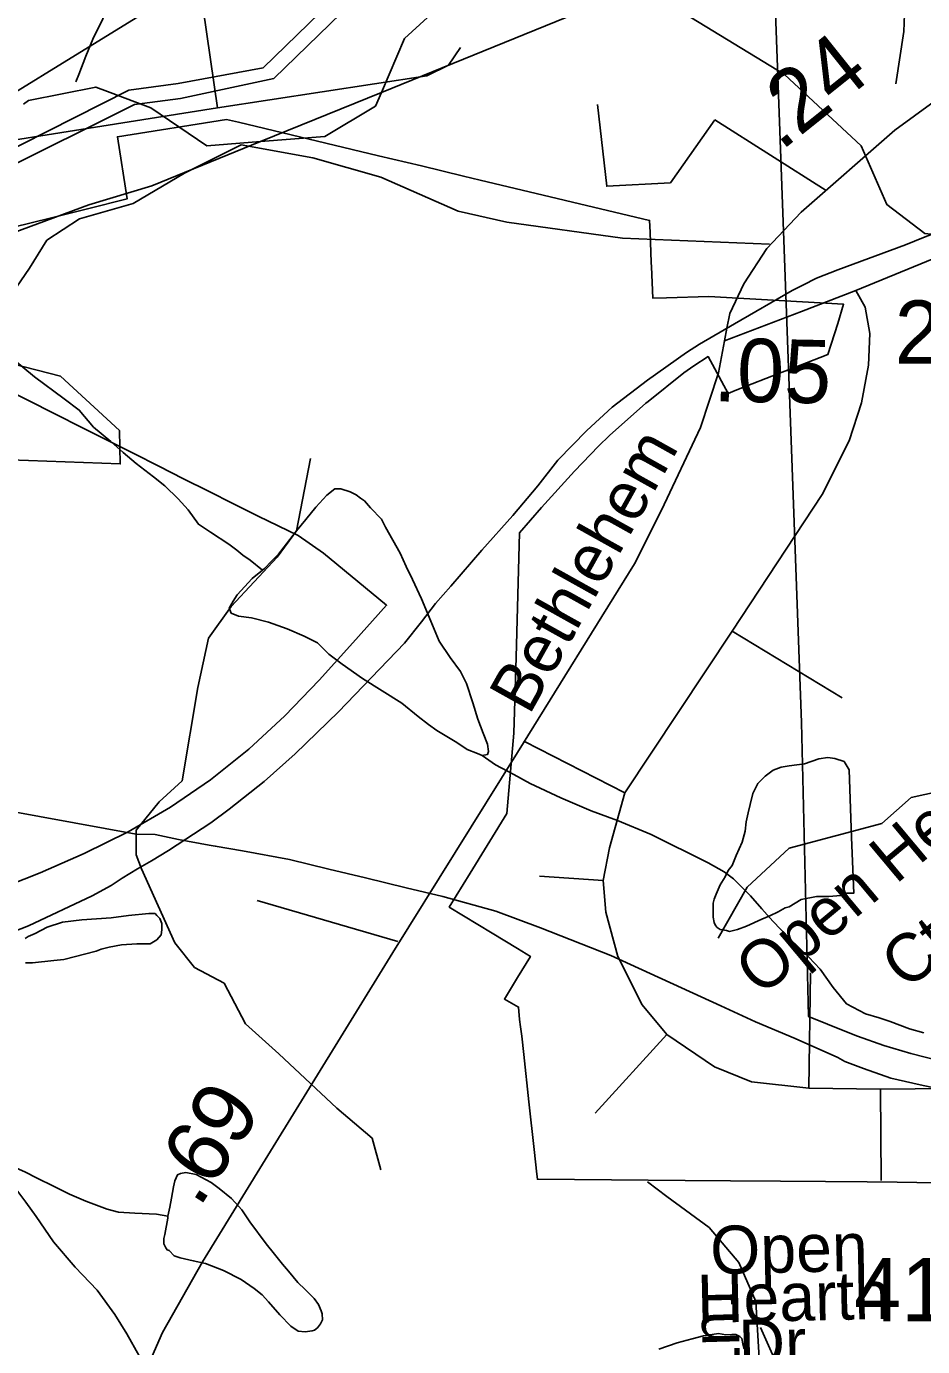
# Model space of a CAD drawing. Extents: x 2169602 to 2449496, y 721995 to 810662.
# Drawn here: x 2391367 to 2393135, y 804152 to 806757 of the extents above; entities that cross this region are included whole.
import ezdxf

# ---------------------------------------------------------------- set-up
doc = ezdxf.new("R2010")
doc.units = 0
doc.layers.add('Default', color=7, linetype='Continuous')

msp = doc.modelspace()

# ---------------------------------------------------------------- linework, layer by layer
at = {"layer": 'Default'}
for p, q in [((2392580.3, 806835.4), (2392067.6, 806626.8)), ((2391527.1, 806628.9), (2391586.4, 806606.4)), ((2392067.6, 806626.8), (2391829.1, 806529.8)), ((2391586.4, 806606.4), (2391612.6, 806596.5)), ((2392725.6, 806573.1), (2392638.2, 806448.5)), ((2392944.9, 806433.4), (2392725.6, 806573.1)), ((2392543.3, 806339.1), (2392314.9, 806370.8)), ((2393004, 806236), (2393281.6, 806350.5)), ((2392833.4, 806327.5), (2392543.3, 806339.1)), ((2392968, 806276.6), (2393101.4, 806326)), ((2392695.4, 806129.8), (2392764.1, 806170.5)), ((2392099.7, 804950.8), (2391822.3, 805031.9)), ((2391646, 804409), (2391624.1, 804412.8))]:
    msp.add_line(p, q, dxfattribs=at)
for points in [[(2391306.5, 806466.6), (2391580.7, 806603.4), (2391671.2, 806615.2), (2391855.2, 806654.1), (2392076.5, 806869.3), (2392429, 807051.7), (2392765.5, 807215.9), (2392830.2, 807238.5), (2392846, 806766.4), (2392896.5, 805383.2), (2392910.2, 804803.1), (2392985.5, 804772.6), (2393006.7, 804764.2), (2393059.2, 804746.1), (2393112.5, 804730.1), (2393166.2, 804716.1), (2393220.5, 804704.1), (2393242.7, 804699.7), (2393269.2, 804694.2), (2393329.5, 804686.7), (2393433.5, 804681.9), (2393504.7, 804684.1)], [(2391306.5, 806466.6), (2391580.7, 806603.4), (2391671.2, 806615.2), (2391855.2, 806654.1), (2392076.5, 806869.3), (2392429, 807051.7), (2392765.5, 807215.9), (2392830.2, 807238.5), (2392846, 806766.4), (2392896.5, 805383.2), (2392910.2, 804803.1), (2392985.5, 804772.6), (2393006.7, 804764.2), (2393059.2, 804746.1), (2393112.5, 804730.1), (2393166.2, 804716.1), (2393220.5, 804704.1), (2393242.7, 804699.7), (2393269.2, 804694.2), (2393329.5, 804686.7), (2393433.5, 804681.9), (2393504.7, 804684.1)], [(2391611.8, 806941.8), (2391606, 806939.8), (2391586.3, 806913.6), (2391564.2, 806874.7), (2391545.5, 806832.1), (2391530.2, 806798.3), (2391518.1, 806772.2), (2391498.4, 806732.2), (2391484.6, 806698.2), (2391470.5, 806662.1), (2391464.7, 806648)], [(2391744.2, 806596.2), (2391693.9, 806942.4)], [(2391302.5, 806496.6), (2391569.5, 806631.3), (2391666.5, 806644.7), (2391834.5, 806675.6), (2392058.7, 806893.9)], [(2391302.5, 806496.6), (2391569.5, 806631.3), (2391666.5, 806644.7), (2391834.5, 806675.6), (2392058.7, 806893.9)], [(2393093.3, 806895.8), (2393101.2, 806816.3), (2393098.6, 806747.4), (2393082.7, 806644)], [(2392067.6, 806626.8), (2392113.1, 806733.3), (2392204, 806816.8), (2392222.1, 806872.4)], [(2393763.4, 806849), (2393609.6, 806863.6), (2393538.4, 806853.2), (2393452.6, 806816.5), (2393330.7, 806734.8), (2393080.6, 806552.6), (2392895.9, 806390.3), (2392827.9, 806319.1), (2392782.9, 806249), (2392754.9, 806190.9), (2392749.4, 806161.5)], [(2393194.1, 806342.4), (2393140, 806348.2), (2393065, 806405.5), (2393014.1, 806521.4), (2392863, 806662.2), (2392580.3, 806835.4)], [(2391643.7, 806811.6), (2391144.7, 806504.4)], [(2391643.7, 806811.6), (2391144.7, 806504.4)], [(2391744.2, 806596.2), (2392157.4, 806659.8), (2392199.8, 806681), (2392223.7, 806715.5)], [(2391361.7, 806603.8), (2391371, 806610.8), (2391504.1, 806637.6), (2391527.1, 806628.9)], [(2391829.1, 806529.8), (2391956, 806539.7), (2392056.1, 806600.1), (2392067.6, 806626.8)], [(2390891.2, 806474.3), (2390925.7, 806474.3), (2391005.1, 806479.6), (2391744.2, 806596.2)], [(2391612.6, 806596.5), (2391723.1, 806521.6), (2391829.1, 806529.8)], [(2392638.2, 806448.5), (2392512.1, 806441.8), (2392494, 806603.2)], [(2391341.7, 806360.9), (2391413.7, 806378.8), (2391487.7, 806397.3), (2391565.7, 806416.6), (2391546.7, 806539.3), (2391761.7, 806573.6), (2391785.4, 806568), (2392062.2, 806501.8), (2392146.4, 806481.8), (2392229.4, 806461.9), (2392262.4, 806454), (2392596.7, 806374.2), (2392597.7, 806351.3), (2392600.2, 806291.4), (2392600.7, 806282.8), (2392603.4, 806220.7), (2392630.2, 806221.6), (2392713.9, 806224.4), (2392979.7, 806208.8), (2392967.9, 806171.1), (2392948.7, 806109.4), (2392879.7, 806083), (2392858.2, 806074.8), (2392825.9, 806062.2), (2392799.2, 806051.6), (2392788.7, 806047.6), (2392760.9, 806036.6), (2392751.7, 806033), (2392712.2, 806105.4), (2392683.9, 806087.2), (2392664.4, 806073.3), (2392593.9, 806017.1), (2392589.4, 806013.3), (2392517.4, 805949.8), (2392495.7, 805929), (2392448.4, 805879.3), (2392383.2, 805807.4), (2392339.9, 805757.9), (2392333.4, 805512.2), (2392329.2, 805362.6), (2392315.4, 805203.5), (2392242.7, 805085.7), (2392201.4, 805018.9), (2392285.9, 804967.6), (2392336.2, 804937.2), (2392361.7, 804921.7), (2392336.2, 804879.8), (2392310.4, 804837.6), (2392338.2, 804821.5), (2392340.2, 804797.3), (2392342.2, 804782.4), (2392344.4, 804764), (2392348.7, 804728.3), (2392358.7, 804634.9), (2392368.9, 804540.4), (2392374.4, 804491.8), (2392375.4, 804481.8), (2392521.4, 804480.5), (2392666.7, 804479.3), (2392756.7, 804478.6)], [(2391341.7, 806360.9), (2391413.7, 806378.8), (2391487.7, 806397.3), (2391565.7, 806416.6), (2391546.7, 806539.3), (2391761.7, 806573.6), (2391785.4, 806568), (2392062.2, 806501.8), (2392146.4, 806481.8), (2392229.4, 806461.9), (2392262.4, 806454), (2392596.7, 806374.2), (2392597.7, 806351.3), (2392600.2, 806291.4), (2392600.7, 806282.8), (2392603.4, 806220.7), (2392630.2, 806221.6), (2392713.9, 806224.4), (2392979.7, 806208.8), (2392967.9, 806171.1), (2392948.7, 806109.4), (2392879.7, 806083), (2392858.2, 806074.8), (2392825.9, 806062.2), (2392799.2, 806051.6), (2392788.7, 806047.6), (2392760.9, 806036.6), (2392751.7, 806033), (2392712.2, 806105.4), (2392683.9, 806087.2), (2392664.4, 806073.3), (2392593.9, 806017.1), (2392589.4, 806013.3), (2392517.4, 805949.8), (2392495.7, 805929), (2392448.4, 805879.3), (2392383.2, 805807.4), (2392339.9, 805757.9), (2392333.4, 805512.2), (2392329.2, 805362.6), (2392315.4, 805203.5), (2392242.7, 805085.7), (2392201.4, 805018.9), (2392285.9, 804967.6), (2392336.2, 804937.2), (2392361.7, 804921.7), (2392336.2, 804879.8), (2392310.4, 804837.6), (2392338.2, 804821.5), (2392340.2, 804797.3), (2392342.2, 804782.4), (2392344.4, 804764), (2392348.7, 804728.3), (2392358.7, 804634.9), (2392368.9, 804540.4), (2392374.4, 804491.8), (2392375.4, 804481.8), (2392521.4, 804480.5), (2392666.7, 804479.3), (2392756.7, 804478.6)], [(2391829.1, 806529.8), (2391614.3, 806442.5), (2391490.6, 806405), (2390221, 805935.1), (2390136.1, 805905.1)], [(2391251.7, 806110.4), (2391253, 806114.9), (2391311.1, 806190.5), (2391373.5, 806280.3), (2391407.2, 806335.2), (2391472, 806377.7), (2391578.1, 806407.6), (2391679.1, 806467.5), (2391790.8, 806523.2)], [(2391790.8, 806523.2), (2391932.3, 806497.8), (2392066.2, 806459.5), (2392219.3, 806392.5), (2392314.9, 806370.8)], [(2393101.4, 806326), (2393137.3, 806340.5), (2393195.1, 806363.1)], [(2392764.1, 806170.5), (2392878.3, 806235.8), (2392899.3, 806246.6), (2392926, 806260.2), (2392968, 806276.6)], [(2392744.8, 806136.7), (2392896.7, 806194.8), (2393004, 806236)], [(2393004, 806236), (2393022, 806202.9), (2393031.1, 806150.9), (2393028.8, 806088.6), (2393015.2, 806014), (2392990.4, 805939.5), (2392937.2, 805833.1), (2392759.7, 805563.8)], [(2392749.4, 806161.5), (2392744.8, 806136.7)], [(2391298.4, 804953.5), (2391371, 804982.2), (2391496.6, 805041.2), (2391534.4, 805061.7), (2391556.1, 805075.8), (2391586.1, 805094.2), (2391613.8, 805110.4), (2391647.6, 805130.7), (2391731.1, 805185.6), (2391766.9, 805212.1), (2391836.2, 805266.9), (2391897.7, 805321.4), (2391982.8, 805404.2), (2392113.4, 805539.8), (2392147, 805582.1), (2392174.6, 805618.3), (2392204.3, 805652.7), (2392265.5, 805723.2), (2392326.9, 805792), (2392376.3, 805850.5), (2392415.7, 805900.9), (2392472.7, 805959.5), (2392522.7, 806005.9), (2392592.4, 806059.1), (2392669.5, 806113.5), (2392695.4, 806129.8)], [(2392744.8, 806136.7), (2392732.9, 806073.6), (2392697.4, 805965.7), (2392620.5, 805802.4), (2392567.1, 805696.6), (2392336.4, 805323.8), (2392089.9, 804929.1), (2391833.1, 804511.3), (2391714.8, 804318.6), (2391635.8, 804179.3), (2391561.5, 804009.7), (2391540.6, 803916.5), (2391505.5, 803843.2), (2391448, 803659.9), (2391386.8, 803479.8), (2391371.1, 803380.4), (2391370, 803296.6), (2391381, 803121.7), (2391397.2, 802941.6)], [(2391299.2, 805049.1), (2391394.4, 805086.9), (2391481.2, 805124.5), (2391568.2, 805167.3), (2391651.4, 805216.1), (2391730.7, 805270.3), (2391805.7, 805330.9), (2391876.9, 805396.5), (2391944.7, 805467), (2392011.4, 805540.3), (2392077.9, 805614.6), (2392062.4, 805627.4), (2391953.2, 805717.4), (2391903.2, 805752.1), (2391824.7, 805790.3), (2391775.7, 805815), (2391726.4, 805839.8), (2391677.4, 805864.5), (2391628.2, 805889.3), (2391579.2, 805914), (2391530.2, 805938.8), (2391466.2, 805970.9), (2391434.9, 805986.7), (2391201.2, 806104.6)], [(2391299.2, 805049.1), (2391394.4, 805086.9), (2391481.2, 805124.5), (2391568.2, 805167.3), (2391651.4, 805216.1), (2391730.7, 805270.3), (2391805.7, 805330.9), (2391876.9, 805396.5), (2391944.7, 805467), (2392011.4, 805540.3), (2392077.9, 805614.6), (2392062.4, 805627.4), (2391953.2, 805717.4), (2391903.2, 805752.1), (2391824.7, 805790.3), (2391775.7, 805815), (2391726.4, 805839.8), (2391677.4, 805864.5), (2391628.2, 805889.3), (2391579.2, 805914), (2391530.2, 805938.8), (2391466.2, 805970.9), (2391434.9, 805986.7), (2391201.2, 806104.6)], [(2391251.7, 806110.4), (2391267.2, 806109.6), (2391434.3, 806066.8), (2391551.1, 805959.4), (2391552.2, 805893.8), (2391335.2, 805901.5), (2391216.4, 805988.1)], [(2391617.9, 805868.3), (2391583.9, 805894.2), (2391557.8, 805916.4), (2391533.8, 805938.2), (2391499.8, 805966.1), (2391471.5, 806000), (2391441.6, 806022), (2391383.3, 806065.6), (2391333.1, 806107.3)], [(2391583.9, 805163.1), (2391583.9, 805171), (2391629, 805226.6), (2391674.2, 805268.3), (2391705.4, 805452.5), (2391726.3, 805549.8), (2391771.4, 805612.4), (2391861.7, 805709.7), (2391899.9, 805761.8), (2391927.7, 805904.3)], [(2391832.8, 805683.7), (2391808.8, 805703.5), (2391794.5, 805713.5), (2391782.4, 805723.4), (2391766.6, 805735.1), (2391730.5, 805758.8), (2391706.5, 805774.6), (2391686, 805802.9), (2391666.3, 805824.5), (2391640.1, 805850.4), (2391617.9, 805868.3)], [(2392266.5, 805317.9), (2392276.7, 805320), (2392279, 805326.2), (2392276.7, 805340.3), (2392268.3, 805362.3), (2392258.1, 805390.1), (2392248.2, 805422.1), (2392235.7, 805460.1), (2392223.6, 805483.8), (2392203.5, 805511.6), (2392181.8, 805543.7), (2392165, 805583.6), (2392146.7, 805627.3), (2392128.9, 805665.3), (2392116.6, 805691.1), (2392104.5, 805717.3), (2392076, 805769), (2392068, 805784.8), (2392046.3, 805806.8), (2392034.2, 805820.8), (2392026.2, 805826.4), (2392017.8, 805832.5), (2392006.1, 805838.4), (2391987.8, 805844.4), (2391975.5, 805844.2), (2391959.9, 805832), (2391938, 805808.1), (2391918.3, 805783.9), (2391900.3, 805761.9), (2391880.6, 805735.7), (2391864.4, 805715.8), (2391850.6, 805701.7), (2391836.9, 805687.5), (2391832.8, 805683.7)], [(2391832.8, 805683.7), (2391812.7, 805667.3), (2391783, 805635.2), (2391775.2, 805623), (2391767.2, 805609.2), (2391771.1, 805599.3), (2391785.4, 805593.1), (2391811.1, 805589.6), (2391845.1, 805581.6), (2391881.6, 805568), (2391915.2, 805554), (2391941.5, 805540.3), (2391963.8, 805518.3), (2391989.9, 805498.5), (2392030.1, 805470.5), (2392108.2, 805421.4), (2392140, 805395.4), (2392160.3, 805379.4), (2392176.7, 805367.6), (2392196.8, 805355.6), (2392216.5, 805343.8), (2392236.8, 805330.1), (2392257.1, 805322.2), (2392266.5, 805317.9)], [(2392759.7, 805563.8), (2392548, 805244.2)], [(2392759.7, 805563.8), (2392976.8, 805432)], [(2390262.1, 805404.2), (2391583.9, 805163.1), (2391621, 805162), (2391667.5, 805152.7), (2391727.6, 805141.3), (2391739.6, 805139.4), (2391793.8, 805129.9), (2391886, 805112.8), (2391964.2, 805093.8), (2392036.4, 805076.5), (2392116.6, 805057.3), (2392188.9, 805040), (2392293.1, 805011.1), (2392381.6, 804978.1), (2392520, 804923.4), (2392737.2, 804823.8), (2392805.5, 804792.6), (2392883.8, 804759.4), (2392968.2, 804722.3), (2392982.3, 804714.4), (2393018.6, 804700.7), (2393072.8, 804681.3), (2393130.9, 804668), (2393205, 804652.6)], [(2392548, 805244.2), (2392350, 805345.9)], [(2393137.8, 804771.1), (2393109.7, 804779), (2393071.5, 804792.9), (2393049.6, 804800.7), (2393023.1, 804808.4), (2392985.2, 804828.3), (2392959.2, 804860.2), (2392933.3, 804896.2), (2392910.8, 804919.9), (2392872.4, 804957.7), (2392840.2, 804991.4), (2392818.3, 805015.4), (2392795.9, 805041.1), (2392782, 805054.9), (2392762.1, 805075), (2392743.9, 805088.7), (2392712.1, 805106.5), (2392599.7, 805162), (2392533.3, 805189.6), (2392481.4, 805209.1), (2392421.5, 805234.9), (2392361, 805262.7), (2392329.2, 805280.4), (2392292.9, 805300.1), (2392266.5, 805317.9)], [(2392995.5, 805156.4), (2392990.6, 805290.2), (2392980.6, 805306.3), (2392962.3, 805312.3), (2392948.2, 805314), (2392930.5, 805311.8), (2392902.4, 805301.9), (2392872.3, 805297.5), (2392856.7, 805295.4), (2392840.9, 805289.3), (2392824.7, 805277.1), (2392810.6, 805263), (2392800.7, 805243), (2392795, 805221.2), (2392791.1, 805205.1), (2392787.2, 805187), (2392785.6, 805169), (2392779.2, 805146.9), (2392767.7, 805121), (2392759.7, 805101.2), (2392751.7, 805091), (2392746, 805078.9), (2392735.9, 805063), (2392727.9, 805044.7), (2392724, 805034.7), (2392722.4, 805026.9), (2392722.4, 805016.7), (2392722, 805004.6), (2392722.4, 804998.9), (2392724.5, 804988.9), (2392726.5, 804982.9), (2392730.4, 804978.6), (2392736.1, 804974.9), (2392748.7, 804973), (2392754.2, 804971), (2392762.2, 804973), (2392770.2, 804975), (2392788.2, 804981.2), (2392818.2, 804995.4), (2392834.2, 805001.5), (2392850.4, 805009.6), (2392864.1, 805017.7), (2392872.1, 805019.7), (2392896.1, 805033.9), (2392926, 805039.9), (2392950.2, 805039.9), (2392974, 805042), (2392986.1, 805046.2), (2392999.6, 805046.2), (2392995.5, 805156.4)], [(2393325.8, 805202), (2393263.1, 805268.2), (2393113.2, 805235.2), (2393055.2, 805183.9), (2392872.1, 805135.3), (2392789.3, 805058.2), (2392732.2, 804957.7)], [(2392548, 805244.2), (2392517.5, 805135.8), (2392505, 805071.3)], [(2391865.2, 804729.6), (2391799.2, 804788.7), (2391757.5, 804868.6), (2391698.5, 804899.9), (2391660.3, 804948.6), (2391594.3, 805094.5), (2391583.9, 805122.3), (2391583.9, 805163.1)], [(2392505, 805071.3), (2392379.5, 805080.3)], [(2392505, 805071.3), (2392510.7, 805009), (2392534.4, 804921.3), (2392581.9, 804826.3), (2392630.6, 804767.5)], [(2391364.8, 804957.2), (2391370.9, 804961.1), (2391384.6, 804967.2), (2391408.4, 804979.4), (2391438.6, 804989.5), (2391476.7, 804993.8), (2391534.7, 804998), (2391568.6, 805002.2), (2391608.8, 805006.3), (2391620.9, 805006.5), (2391624.8, 805002.6), (2391630.5, 804996.5), (2391634.4, 804986.6), (2391634.6, 804974.4), (2391633, 804964.5), (2391624.8, 804954.4), (2391611.2, 804946.3), (2391584.8, 804946.3), (2391554.8, 804944.3), (2391530.6, 804939.8), (2391514.6, 804936.2), (2391505, 804932)], [(2391505, 804932), (2391441.2, 804915.7), (2391421.3, 804913.4), (2391378.9, 804909.2), (2391371.3, 804909.2), (2391365.4, 804909.2)], [(2392911.2, 804661.8), (2392914.6, 804889.2)], [(2392630.6, 804767.5), (2392489.2, 804612.4)], [(2392630.6, 804767.5), (2392724.6, 804703.6), (2392798.1, 804674.2), (2392911.2, 804661.8)], [(2391865.2, 804729.6), (2391979.8, 804621.9), (2392049.2, 804562.8), (2392066.6, 804500.2)], [(2392911.2, 804661.8), (2393052.6, 804659.5)], [(2393052.6, 804659.5), (2393258.4, 804661.8)], [(2393052.6, 804659.5), (2393053.7, 804479.6)], [(2391624.1, 804412.8), (2391580.8, 804415.2), (2391548.6, 804416.9), (2391526.3, 804423.1), (2391484.4, 804438.8), (2391452.2, 804452.5), (2391420.4, 804468.3), (2391388.3, 804484.1), (2391363.9, 804496.3), (2391314, 804518.1)], [(2391625.9, 804084.7), (2391616.1, 804094.7), (2391589.8, 804133.2), (2391565.6, 804177), (2391541.4, 804215.1), (2391507, 804262.9), (2391463.1, 804308.5), (2391420.9, 804358.3), (2391386.6, 804408.1), (2391366.3, 804436.3), (2391342.1, 804468), (2391314, 804518.1)], [(2391646, 804409), (2391650.1, 804426.7), (2391653.6, 804444.8), (2391657.7, 804466.9), (2391659.7, 804478.7), (2391665.5, 804490.8), (2391671.4, 804493.2), (2391681.5, 804494.9), (2391701.8, 804491), (2391731.7, 804475.2), (2391747.7, 804463.4), (2391771.5, 804443.6), (2391792.2, 804421.8), (2391808.2, 804397.9), (2391840.4, 804354.1), (2391856.6, 804334.2), (2391872.4, 804314.3), (2391884.5, 804300.3), (2391902.5, 804278.1), (2391916.9, 804264.2), (2391934.7, 804246.5), (2391943.3, 804234.6), (2391948.9, 804222.4), (2391950.9, 804216.5), (2391951.1, 804204.7), (2391947.2, 804196.7), (2391941.3, 804188.7), (2391935.3, 804184.3), (2391931.2, 804182.5), (2391917.3, 804180.6), (2391903.1, 804182.3), (2391889, 804192.1), (2391867.3, 804214.1), (2391845.1, 804239.8), (2391832.6, 804253.8), (2391816.8, 804265.9), (2391790.8, 804283.7), (2391756.3, 804301.5), (2391720.4, 804315.4), (2391696.4, 804321.1), (2391670.6, 804327), (2391658.5, 804330.9), (2391648.7, 804340.9), (2391644.8, 804342.7), (2391642.3, 804346.7), (2391638.2, 804354.6), (2391638.2, 804364.8), (2391640.5, 804373), (2391646.2, 804404.9), (2391646, 804409)], [(2392567.8, 803177.5), (2392564.6, 803294.8), (2392577.2, 803362.8), (2392621.1, 803429.8), (2392706.9, 803505.2), (2392763.4, 803570.2), (2392803.2, 803645.6), (2392815.8, 803729.3), (2392823.1, 803961.8), (2392812.6, 804139.8), (2392806.3, 804240.3), (2392772.9, 804317.8), (2392714.3, 804386.9), (2392630.5, 804447.7), (2392592.4, 804477)], [(2392756.7, 804478.6), (2392855.2, 804477.8), (2392944.2, 804477.2), (2393025.9, 804476.6), (2393085.2, 804476.1), (2393163.2, 804475.1)], [(2392756.7, 804478.6), (2392855.2, 804477.8), (2392944.2, 804477.2), (2393025.9, 804476.6), (2393085.2, 804476.1), (2393163.2, 804475.1)], [(2392815.4, 804189.4), (2392849.9, 804112.4), (2392870.4, 804066.6), (2392896.6, 804016), (2392920, 803978.7), (2392954.3, 803905.5), (2392976.7, 803859.8), (2392989, 803824), (2392997.6, 803784), (2393010.1, 803722.1), (2393018.6, 803686.2), (2393039.4, 803608.3), (2393051.7, 803576.5), (2393112.5, 803461.3)], [(2392615.2, 804146.2), (2392651.3, 804158.7), (2392681, 804166.7), (2392702.9, 804172.7), (2392732.9, 804177.1), (2392747, 804175), (2392758.9, 804175.2), (2392767.1, 804175.2), (2392774.9, 804171.2), (2392779, 804167.3), (2392780.6, 804157.3), (2392783.3, 804147.2)]]:
    msp.add_lwpolyline(points, dxfattribs=at)

# ---------------------------------------------------------------- texts
for s, height, rotation, p in [('.24', 125, 38.6781, (2392855.7, 806509.8)), ('.05', 125, 358.8958, (2392721.8, 806017.4)), ('Bethlehem', 95, 60.8133, (2392359.4, 805396)), ('Open Hearth', 95, 39.9058, (2392817, 804840.7)), ('Ct.', 95, 39.9058, (2393104.6, 804853.1)), ('.69', 125, 57.2819, (2391707.9, 804423.2)), ('Open', 95, 1.2745, (2392717.4, 804294.4)), ('Hearth', 95, 1.2745, (2392691.2, 804198.1)), ('Ln.', 95, 91.5231, (2392776.1, 804082.7)), ('Dr.', 95, 1.2745, (2392773.2, 804109.5))]:
    msp.add_text(s, height=height, rotation=rotation, dxfattribs=at).set_placement(p)
for s, p in [('2563', (2393080.4, 806091.3)), ('4140', (2393000, 804201.5))]:
    msp.add_text(s, height=125, dxfattribs=at).set_placement(p)

doc.saveas('drawing.dxf')
